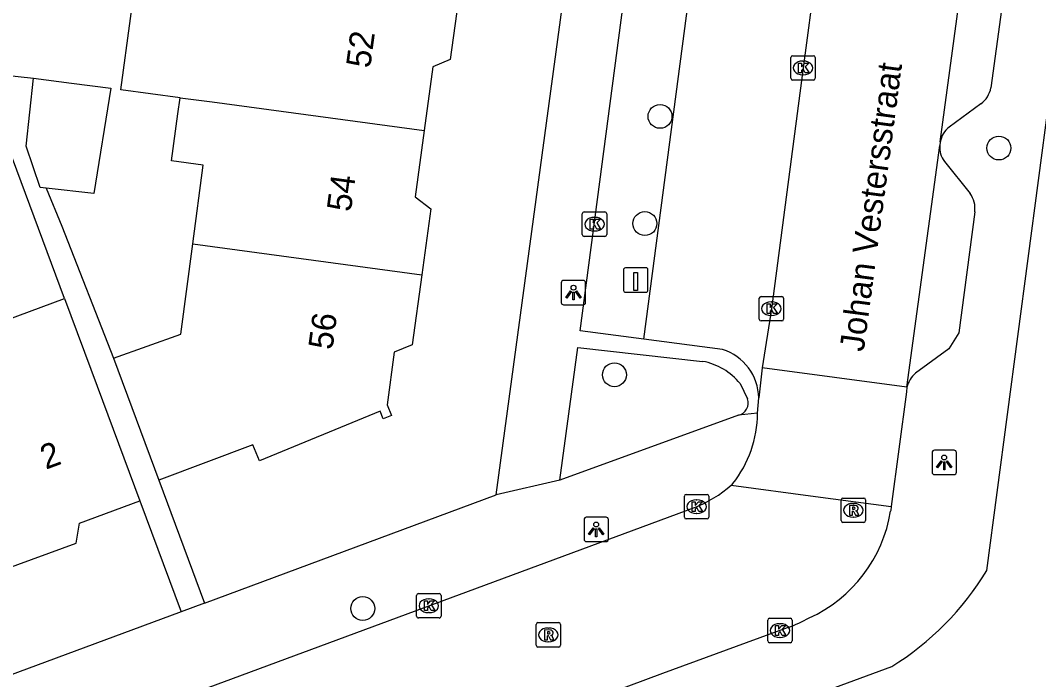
# Model space of a CAD drawing. Extents: x 161258 to 161838, y 380836 to 381727.
# Drawn here: x 161697.93 to 161739.61, y 381501.61 to 381528.61 of the extents above; entities that cross this region are included whole.
import ezdxf

# ---------------------------------------------------------------- set-up
doc = ezdxf.new("R2010")
doc.units = 0
for name, color, linetype in [('IMGEO_Boom', 7, 'Continuous'), ('IMGEO_Kolk', 7, 'Continuous'), ('IMGEO_Laadpaal', 7, 'Continuous'), ('IMGEO_Lichtpunt', 7, 'Continuous'), ('IMGEO_Openbare_ruimte_label', 7, 'Continuous'), ('IMGEO_Pand', 7, 'Continuous'), ('IMGEO_Pand_nummerreeks', 7, 'Continuous'), ('IMGEO_Rijbaan_lokaal_open', 7, 'Continuous'), ('IMGEO_Rioolput', 7, 'Continuous'), ('IMGEO_Voetpad_open', 7, 'Continuous')]:
    doc.layers.add(name, color=color, linetype=linetype)

msp = doc.modelspace()

# ---------------------------------------------------------------- linework, layer by layer
at = {"layer": 'IMGEO_Boom'}
for centre in [(161724.112, 381524.675), (161737.98, 381523.378), (161723.492, 381520.285), (161722.245, 381514.094), (161711.945, 381504.521)]:
    msp.add_circle(centre, 0.489, dxfattribs=at)
at = {"layer": 'IMGEO_Kolk'}
for p, q in [((161729.464, 381526.234), (161729.464, 381527.086)), ((161729.539, 381527.16), (161730.391, 381527.16)), ((161729.952, 381526.94), (161729.977, 381526.94)), ((161730.465, 381527.086), (161730.465, 381526.234)), ((161730.391, 381526.16), (161729.539, 381526.16)), ((161729.975, 381526.38), (161729.95, 381526.38)), ((161720.931, 381519.835), (161720.931, 381520.687)), ((161721.006, 381520.761), (161721.858, 381520.761)), ((161721.932, 381520.687), (161721.932, 381519.835)), ((161721.419, 381520.541), (161721.444, 381520.541)), ((161721.442, 381519.981), (161721.417, 381519.981)), ((161721.858, 381519.761), (161721.006, 381519.761)), ((161728.17, 381516.373), (161728.17, 381517.225)), ((161728.245, 381517.299), (161729.097, 381517.299)), ((161728.658, 381517.079), (161728.683, 381517.079)), ((161729.171, 381517.225), (161729.171, 381516.373)), ((161728.681, 381516.519), (161728.656, 381516.519)), ((161729.097, 381516.299), (161728.245, 381516.299)), ((161725.109, 381508.266), (161725.109, 381509.118)), ((161725.184, 381509.192), (161726.036, 381509.192)), ((161726.11, 381509.118), (161726.11, 381508.266)), ((161725.597, 381508.972), (161725.622, 381508.972)), ((161726.036, 381508.192), (161725.184, 381508.192)), ((161725.62, 381508.412), (161725.595, 381508.412)), ((161714.149, 381504.207), (161714.149, 381505.059)), ((161714.224, 381505.133), (161715.076, 381505.133)), ((161714.637, 381504.913), (161714.662, 381504.913)), ((161715.15, 381505.059), (161715.15, 381504.207)), ((161715.076, 381504.133), (161714.224, 381504.133)), ((161714.66, 381504.353), (161714.635, 381504.353)), ((161728.518, 381503.194), (161728.518, 381504.046)), ((161728.593, 381504.12), (161729.445, 381504.12)), ((161729.519, 381504.046), (161729.519, 381503.194)), ((161729.006, 381503.9), (161729.031, 381503.9)), ((161729.029, 381503.34), (161729.004, 381503.34)), ((161729.445, 381503.12), (161728.593, 381503.12))]:
    msp.add_line(p, q, dxfattribs=at)
for points in [[(161729.464, 381526.234), (161729.464, 381527.086)], [(161729.539, 381527.16), (161730.391, 381527.16)], [(161730.465, 381527.086), (161730.465, 381526.234)], [(161729.785, 381526.86), (161729.908, 381526.86), (161729.908, 381526.709), (161730.038, 381526.86), (161730.202, 381526.86), (161730.056, 381526.709), (161730.209, 381526.46), (161730.057, 381526.46), (161729.972, 381526.624), (161729.908, 381526.557), (161729.908, 381526.46), (161729.785, 381526.46), (161729.785, 381526.86)], [(161730.391, 381526.16), (161729.539, 381526.16)], [(161720.931, 381519.835), (161720.931, 381520.687)], [(161721.006, 381520.761), (161721.858, 381520.761)], [(161721.932, 381520.687), (161721.932, 381519.835)], [(161721.252, 381520.461), (161721.375, 381520.461), (161721.375, 381520.31), (161721.505, 381520.461), (161721.669, 381520.461), (161721.523, 381520.31), (161721.676, 381520.061), (161721.524, 381520.061), (161721.439, 381520.225), (161721.375, 381520.158), (161721.375, 381520.061), (161721.252, 381520.061), (161721.252, 381520.461)], [(161721.858, 381519.761), (161721.006, 381519.761)], [(161728.17, 381516.373), (161728.17, 381517.225)], [(161728.245, 381517.299), (161729.097, 381517.299)], [(161728.491, 381516.999), (161728.614, 381516.999), (161728.614, 381516.848), (161728.744, 381516.999), (161728.908, 381516.999), (161728.762, 381516.848), (161728.915, 381516.599), (161728.763, 381516.599), (161728.678, 381516.763), (161728.614, 381516.696), (161728.614, 381516.599), (161728.491, 381516.599), (161728.491, 381516.999)], [(161729.171, 381517.225), (161729.171, 381516.373)], [(161729.097, 381516.299), (161728.245, 381516.299)], [(161725.109, 381508.266), (161725.109, 381509.118)], [(161725.184, 381509.192), (161726.036, 381509.192)], [(161726.11, 381509.118), (161726.11, 381508.266)], [(161725.43, 381508.892), (161725.553, 381508.892), (161725.553, 381508.741), (161725.683, 381508.892), (161725.847, 381508.892), (161725.701, 381508.741), (161725.854, 381508.492), (161725.702, 381508.492), (161725.617, 381508.656), (161725.553, 381508.589), (161725.553, 381508.492), (161725.43, 381508.492), (161725.43, 381508.892)], [(161726.036, 381508.192), (161725.184, 381508.192)], [(161714.149, 381504.207), (161714.149, 381505.059)], [(161714.224, 381505.133), (161715.076, 381505.133)], [(161714.47, 381504.833), (161714.593, 381504.833), (161714.593, 381504.682), (161714.723, 381504.833), (161714.887, 381504.833), (161714.741, 381504.682), (161714.894, 381504.433), (161714.742, 381504.433), (161714.657, 381504.597), (161714.593, 381504.53), (161714.593, 381504.433), (161714.47, 381504.433), (161714.47, 381504.833)], [(161715.15, 381505.059), (161715.15, 381504.207)], [(161715.076, 381504.133), (161714.224, 381504.133)], [(161728.518, 381503.194), (161728.518, 381504.046)], [(161728.593, 381504.12), (161729.445, 381504.12)], [(161729.519, 381504.046), (161729.519, 381503.194)], [(161728.839, 381503.82), (161728.962, 381503.82), (161728.962, 381503.669), (161729.092, 381503.82), (161729.256, 381503.82), (161729.11, 381503.669), (161729.263, 381503.42), (161729.111, 381503.42), (161729.026, 381503.584), (161728.962, 381503.517), (161728.962, 381503.42), (161728.839, 381503.42), (161728.839, 381503.82)], [(161729.445, 381503.12), (161728.593, 381503.12)]]:
    msp.add_lwpolyline(points, dxfattribs=at)
for centre, start, end in [((161729.541, 381527.084), 91.552, 178.448), ((161729.541, 381527.084), 91.552, 178.448), ((161730.389, 381527.084), 1.552, 88.448), ((161730.389, 381527.084), 1.552, 88.448), ((161729.541, 381526.236), 181.552, 268.448), ((161729.541, 381526.236), 181.552, 268.448), ((161730.389, 381526.236), 271.552, 358.448), ((161730.389, 381526.236), 271.552, 358.448), ((161721.008, 381520.685), 91.552, 178.448), ((161721.008, 381520.685), 91.552, 178.448), ((161721.856, 381520.685), 1.552, 88.448), ((161721.856, 381520.685), 1.552, 88.448), ((161721.008, 381519.837), 181.552, 268.448), ((161721.008, 381519.837), 181.552, 268.448), ((161721.856, 381519.837), 271.552, 358.448), ((161721.856, 381519.837), 271.552, 358.448), ((161728.247, 381517.223), 91.552, 178.448), ((161728.247, 381517.223), 91.552, 178.448), ((161729.095, 381517.223), 1.552, 88.448), ((161729.095, 381517.223), 1.552, 88.448), ((161728.247, 381516.375), 181.552, 268.448), ((161728.247, 381516.375), 181.552, 268.448), ((161729.095, 381516.375), 271.552, 358.448), ((161729.095, 381516.375), 271.552, 358.448), ((161725.186, 381509.116), 91.552, 178.448), ((161725.186, 381509.116), 91.552, 178.448), ((161726.034, 381509.116), 1.552, 88.448), ((161726.034, 381509.116), 1.552, 88.448), ((161725.186, 381508.268), 181.552, 268.448), ((161725.186, 381508.268), 181.552, 268.448), ((161726.034, 381508.268), 271.552, 358.448), ((161726.034, 381508.268), 271.552, 358.448), ((161714.226, 381505.057), 91.552, 178.448), ((161714.226, 381505.057), 91.552, 178.448), ((161715.074, 381505.057), 1.552, 88.448), ((161715.074, 381505.057), 1.552, 88.448), ((161714.226, 381504.209), 181.552, 268.448), ((161714.226, 381504.209), 181.552, 268.448), ((161715.074, 381504.209), 271.552, 358.448), ((161715.074, 381504.209), 271.552, 358.448), ((161728.595, 381504.044), 91.552, 178.448), ((161728.595, 381504.044), 91.552, 178.448), ((161729.443, 381504.044), 1.552, 88.448), ((161729.443, 381504.044), 1.552, 88.448), ((161728.595, 381503.196), 181.552, 268.448), ((161728.595, 381503.196), 181.552, 268.448), ((161729.443, 381503.196), 271.552, 358.448), ((161729.443, 381503.196), 271.552, 358.448)]:
    msp.add_arc(centre, 0.0765, start, end, dxfattribs=at)
for centre, major_axis, ratio, start_param, end_param in [((161729.951, 381526.66), (-0.387, 0.002), 0.722429, 4.712389, 7.853982), ((161729.976, 381526.66), (-0.39, 0.002), 0.717154, 1.570796, 4.712389), ((161721.418, 381520.261), (-0.387, 0.002), 0.722429, 4.712389, 7.853982), ((161721.443, 381520.261), (-0.39, 0.002), 0.717154, 1.570796, 4.712389), ((161728.657, 381516.799), (-0.387, 0.002), 0.722429, 4.712389, 7.853982), ((161728.682, 381516.799), (-0.39, 0.002), 0.717154, 1.570796, 4.712389), ((161725.596, 381508.692), (-0.387, 0.002), 0.722429, 4.712389, 7.853982), ((161725.621, 381508.692), (-0.39, 0.002), 0.717154, 1.570796, 4.712389), ((161714.636, 381504.633), (-0.387, 0.002), 0.722429, 4.712389, 7.853982), ((161714.661, 381504.633), (-0.39, 0.002), 0.717154, 1.570796, 4.712389), ((161729.005, 381503.62), (-0.387, 0.002), 0.722429, 4.712389, 7.853982), ((161729.03, 381503.62), (-0.39, 0.002), 0.717154, 1.570796, 4.712389)]:
    msp.add_ellipse(centre, major_axis=major_axis, ratio=ratio, start_param=start_param, end_param=end_param, dxfattribs=at)
at = {"layer": 'IMGEO_Laadpaal'}
for p, q in [((161722.619, 381518.387), (161722.619, 381517.546)), ((161722.619, 381518.387), (161722.619, 381517.546)), ((161723.535, 381518.471), (161722.694, 381518.471)), ((161723.535, 381518.471), (161722.694, 381518.471)), ((161723.619, 381517.555), (161723.619, 381518.396)), ((161723.619, 381517.555), (161723.619, 381518.396)), ((161722.703, 381517.471), (161723.544, 381517.471)), ((161722.703, 381517.471), (161723.544, 381517.471))]:
    msp.add_line(p, q, dxfattribs=at)
msp.add_lwpolyline([(161723.034, 381518.284), (161723.194, 381518.284), (161723.194, 381517.551), (161723.034, 381517.551), (161723.034, 381518.284)], dxfattribs=at)
for centre, start, end in [((161722.697, 381518.393), 92.4484, 184.2845), ((161722.697, 381518.393), 92.4484, 184.2845), ((161723.541, 381518.393), 2.4484, 94.2845), ((161723.541, 381518.393), 2.4484, 94.2845), ((161722.697, 381517.549), 182.4484, 274.2845), ((161722.697, 381517.549), 182.4484, 274.2845), ((161723.541, 381517.549), 272.4484, 4.2845), ((161723.541, 381517.549), 272.4484, 4.2845)]:
    msp.add_arc(centre, 0.0779, start, end, dxfattribs=at)
at = {"layer": 'IMGEO_Lichtpunt'}
for p, q in [((161720.071, 381517.862), (161720.071, 381517.055)), ((161720.071, 381517.862), (161720.071, 381517.055)), ((161720.973, 381517.957), (161720.165, 381517.957)), ((161720.973, 381517.957), (161720.165, 381517.957)), ((161721.067, 381517.055), (161721.067, 381517.862)), ((161721.067, 381517.055), (161721.067, 381517.862)), ((161720.165, 381516.961), (161720.973, 381516.961)), ((161720.165, 381516.961), (161720.973, 381516.961)), ((161735.244, 381510.907), (161735.244, 381510.1)), ((161735.244, 381510.907), (161735.244, 381510.1)), ((161736.146, 381511.002), (161735.338, 381511.002)), ((161736.146, 381511.002), (161735.338, 381511.002)), ((161736.24, 381510.1), (161736.24, 381510.907)), ((161736.24, 381510.1), (161736.24, 381510.907)), ((161735.338, 381510.006), (161736.146, 381510.006)), ((161735.338, 381510.006), (161736.146, 381510.006)), ((161721.001, 381508.162), (161721.001, 381507.355)), ((161721.001, 381508.162), (161721.001, 381507.355)), ((161721.903, 381508.257), (161721.095, 381508.257)), ((161721.903, 381508.257), (161721.095, 381508.257)), ((161721.997, 381507.355), (161721.997, 381508.162)), ((161721.997, 381507.355), (161721.997, 381508.162)), ((161721.095, 381507.261), (161721.903, 381507.261)), ((161721.095, 381507.261), (161721.903, 381507.261))]:
    msp.add_line(p, q, dxfattribs=at)
for points in [[(161720.445, 381517.526), (161720.484, 381517.498), (161720.296, 381517.236), (161720.258, 381517.263), (161720.445, 381517.526)], [(161720.547, 381517.478), (161720.594, 381517.478), (161720.594, 381517.156), (161720.547, 381517.156), (161720.547, 381517.478)], [(161720.657, 381517.498), (161720.695, 381517.525), (161720.882, 381517.263), (161720.843, 381517.235), (161720.657, 381517.498)], [(161735.618, 381510.571), (161735.657, 381510.543), (161735.469, 381510.281), (161735.431, 381510.308), (161735.618, 381510.571)], [(161735.72, 381510.523), (161735.767, 381510.523), (161735.767, 381510.201), (161735.72, 381510.201), (161735.72, 381510.523)], [(161735.83, 381510.543), (161735.868, 381510.57), (161736.055, 381510.308), (161736.016, 381510.28), (161735.83, 381510.543)], [(161721.375, 381507.826), (161721.414, 381507.798), (161721.226, 381507.536), (161721.188, 381507.563), (161721.375, 381507.826)], [(161721.477, 381507.778), (161721.524, 381507.778), (161721.524, 381507.456), (161721.477, 381507.456), (161721.477, 381507.778)], [(161721.587, 381507.798), (161721.625, 381507.825), (161721.812, 381507.563), (161721.773, 381507.535), (161721.587, 381507.798)]]:
    msp.add_lwpolyline(points, dxfattribs=at)
for centre in [(161720.57, 381517.66), (161735.743, 381510.705), (161721.5, 381507.96)]:
    msp.add_circle(centre, 0.0994, dxfattribs=at)
for centre, start, end in [((161720.165, 381517.862), 90, 180), ((161720.165, 381517.862), 90, 180), ((161720.973, 381517.862), 0, 90), ((161720.973, 381517.862), 0, 90), ((161720.165, 381517.055), 180, 270), ((161720.165, 381517.055), 180, 270), ((161720.973, 381517.055), 270, 0), ((161720.973, 381517.055), 270, 360), ((161735.338, 381510.907), 90, 180), ((161735.338, 381510.907), 90, 180), ((161736.146, 381510.907), 0, 90), ((161736.146, 381510.907), 0, 90), ((161735.338, 381510.1), 180, 270), ((161735.338, 381510.1), 180, 270), ((161736.146, 381510.1), 270, 0), ((161736.146, 381510.1), 270, 360), ((161721.095, 381508.162), 90, 180), ((161721.095, 381508.162), 90, 180), ((161721.903, 381508.162), 0, 90), ((161721.903, 381508.162), 0, 90), ((161721.095, 381507.355), 180, 270), ((161721.095, 381507.355), 180, 270), ((161721.903, 381507.355), 270, 0), ((161721.903, 381507.355), 270, 360)]:
    msp.add_arc(centre, 0.0946, start, end, dxfattribs=at)
at = {"layer": 'IMGEO_Pand'}
for points in [[(161704.472, 381525.437), (161702.05, 381525.76), (161702.843, 381531.624)], [(161715.917, 381529.873), (161715.529, 381527.004), (161714.809, 381526.709), (161714.457, 381524.101)], [(161698.995, 381521.736), (161698.746, 381521.764), (161698.171, 381523.462), (161698.47, 381526.241)], [(161698.47, 381526.241), (161700.032, 381526.034), (161701.633, 381525.825), (161700.936, 381521.518), (161698.995, 381521.736)], [(161704.991, 381519.451), (161705.417, 381522.678), (161704.123, 381522.851), (161704.383, 381524.779), (161704.472, 381525.437)], [(161704.472, 381525.437), (161704.688, 381525.409), (161705.777, 381525.264), (161714.457, 381524.101)], [(161714.457, 381524.101), (161714.089, 381521.377), (161714.726, 381520.885), (161714.361, 381518.184)], [(161701.746, 381514.78), (161704.502, 381515.75), (161704.991, 381519.451)], [(161704.991, 381519.451), (161714.361, 381518.184)], [(161714.361, 381518.184), (161713.974, 381515.323), (161713.236, 381515.021), (161712.944, 381512.86), (161713.12, 381512.431), (161712.787, 381512.295), (161712.661, 381512.601), (161707.719, 381510.574), (161707.453, 381511.222), (161703.602, 381509.777)], [(161693.998, 381515.089), (161699.745, 381517.223)], [(161699.745, 381517.223), (161701.082, 381513.623), (161702.823, 381508.935)], [(161701.746, 381514.78), (161703.602, 381509.777)], [(161697.277, 381506.112), (161700.213, 381507.202), (161700.352, 381508.018), (161702.823, 381508.935)]]:
    msp.add_lwpolyline(points, dxfattribs=at)
at = {"layer": 'IMGEO_Rijbaan_lokaal_open'}
for points in [[(161735.58, 381523.626), (161737.448, 381537.445)], [(161730.473, 381530.472), (161729.966, 381526.66), (161728.672, 381516.798), (161728.292, 381514.383)], [(161735.58, 381523.626), (161735.56, 381523.476)], [(161734.218, 381513.579), (161735.56, 381523.476)], [(161728.292, 381514.383), (161728.151, 381513.143)], [(161734.218, 381513.579), (161728.292, 381514.383)], [(161734.218, 381513.579), (161734.197, 381513.389), (161733.573, 381508.694)], [(161728.107, 381512.517), (161728.151, 381513.143)], [(161727.024, 381509.572), (161727.058, 381509.605), (161727.093, 381509.638)], [(161727.024, 381509.572), (161730.479, 381509.109), (161733.573, 381508.694)], [(161658.225, 381483.74), (161671.265, 381488.572), (161693.452, 381496.782), (161725.523, 381508.66)], [(161733.573, 381508.694), (161733.551, 381508.53), (161733.548, 381508.51)], [(161729.353, 381503.742), (161729.019, 381503.62), (161724.209, 381501.861), (161701.588, 381493.419)]]:
    msp.add_lwpolyline(points, dxfattribs=at)
for centre, radius, start, end in [((161723.335, 381512.58), 4.773, 321.9479, 359.247), ((161723.726, 381513.308), 4.983, 291.1326, 311.4327), ((161727.791, 381509.437), 5.831, 294.5758, 350.8511), ((161726.46, 381511.258), 8.053, 291.0552, 297.8027)]:
    msp.add_arc(centre, radius, start, end, dxfattribs=at)
at = {"layer": 'IMGEO_Rioolput'}
for p, q in [((161731.599, 381509.046), (161732.451, 381509.046)), ((161731.524, 381508.12), (161731.524, 381508.972)), ((161732.012, 381508.826), (161732.037, 381508.826)), ((161732.525, 381508.972), (161732.525, 381508.12)), ((161732.035, 381508.266), (161732.01, 381508.266)), ((161732.451, 381508.046), (161731.599, 381508.046)), ((161719.041, 381503.016), (161719.041, 381503.868)), ((161719.116, 381503.942), (161719.968, 381503.942)), ((161719.529, 381503.722), (161719.554, 381503.722)), ((161720.042, 381503.868), (161720.042, 381503.016)), ((161719.552, 381503.162), (161719.527, 381503.162)), ((161719.968, 381502.942), (161719.116, 381502.942))]:
    msp.add_line(p, q, dxfattribs=at)
for points in [[(161731.599, 381509.046), (161732.451, 381509.046)], [(161731.524, 381508.12), (161731.524, 381508.972)], [(161732.113, 381508.744), (161731.861, 381508.746), (161731.861, 381508.346)], [(161732.039, 381508.665), (161731.985, 381508.665), (161731.985, 381508.584)], [(161731.985, 381508.584), (161732.037, 381508.584)], [(161732.525, 381508.972), (161732.525, 381508.12)], [(161731.861, 381508.346), (161731.985, 381508.346), (161731.985, 381508.508), (161731.996, 381508.508)], [(161732.043, 381508.479), (161732.114, 381508.346), (161732.254, 381508.346), (161732.189, 381508.472)], [(161732.451, 381508.046), (161731.599, 381508.046)], [(161719.041, 381503.016), (161719.041, 381503.868)], [(161719.116, 381503.942), (161719.968, 381503.942)], [(161719.63, 381503.64), (161719.378, 381503.642), (161719.378, 381503.242)], [(161719.556, 381503.561), (161719.502, 381503.561), (161719.502, 381503.48)], [(161720.042, 381503.868), (161720.042, 381503.016)], [(161719.378, 381503.242), (161719.502, 381503.242), (161719.502, 381503.404), (161719.513, 381503.404)], [(161719.502, 381503.48), (161719.554, 381503.48)], [(161719.56, 381503.375), (161719.631, 381503.242), (161719.771, 381503.242), (161719.706, 381503.368)], [(161719.968, 381502.942), (161719.116, 381502.942)]]:
    msp.add_lwpolyline(points, dxfattribs=at)
for centre, radius, start, end in [((161731.601, 381508.97), 0.0765, 91.552, 178.448), ((161731.601, 381508.97), 0.0765, 91.552, 178.448), ((161732.449, 381508.97), 0.0765, 1.552, 88.448), ((161732.449, 381508.97), 0.0765, 1.552, 88.448), ((161732.021, 381508.773), 0.19, 274.7715, 282.9687), ((161732.045, 381508.569), 0.0964, 77.0061, 93.1865), ((161732.059, 381508.626), 0.0378, 276.6634, 79.6772), ((161732.112, 381508.634), 0.109, 350.3612, 89.416), ((161732.11, 381508.634), 0.112, 277.5842, 350.9817), ((161731.995, 381508.455), 0.0533, 26.0293, 88.6989), ((161732.094, 381508.419), 0.108, 29.5134, 73.7905), ((161731.601, 381508.122), 0.0765, 181.552, 268.448), ((161731.601, 381508.122), 0.0765, 181.552, 268.448), ((161732.449, 381508.122), 0.0765, 271.552, 358.448), ((161732.449, 381508.122), 0.0765, 271.552, 358.448), ((161719.118, 381503.866), 0.0765, 91.552, 178.448), ((161719.118, 381503.866), 0.0765, 91.552, 178.448), ((161719.562, 381503.465), 0.0964, 77.0061, 93.1865), ((161719.629, 381503.53), 0.109, 350.3612, 89.416), ((161719.966, 381503.866), 0.0765, 1.552, 88.448), ((161719.966, 381503.866), 0.0765, 1.552, 88.448), ((161719.512, 381503.351), 0.0533, 26.0293, 88.6989), ((161719.538, 381503.669), 0.19, 274.7715, 282.9687), ((161719.576, 381503.522), 0.0378, 276.6634, 79.6772), ((161719.627, 381503.53), 0.112, 277.5842, 350.9817), ((161719.611, 381503.315), 0.108, 29.5134, 73.7905), ((161719.118, 381503.018), 0.0765, 181.552, 268.448), ((161719.118, 381503.018), 0.0765, 181.552, 268.448), ((161719.966, 381503.018), 0.0765, 271.552, 358.448), ((161719.966, 381503.018), 0.0765, 271.552, 358.448)]:
    msp.add_arc(centre, radius, start, end, dxfattribs=at)
for centre, major_axis, ratio, start_param, end_param in [((161732.011, 381508.546), (-0.387, 0.002), 0.722429, 4.712389, 7.853982), ((161732.036, 381508.546), (-0.39, 0.002), 0.717154, 1.570796, 4.712389), ((161719.528, 381503.442), (-0.387, 0.002), 0.722429, 4.712389, 7.853982), ((161719.553, 381503.442), (-0.39, 0.002), 0.717154, 1.570796, 4.712389)]:
    msp.add_ellipse(centre, major_axis=major_axis, ratio=ratio, start_param=start_param, end_param=end_param, dxfattribs=at)
at = {"layer": 'IMGEO_Voetpad_open'}
for points in [[(161717.412, 381509.172), (161725.791, 381571.18)], [(161723.447, 381515.547), (161720.85, 381515.886), (161720.838, 381515.888), (161724.557, 381544.042), (161725.131, 381548.374), (161727.76, 381548.004)], [(161737.48, 381506.08), (161741.711, 381538.033)], [(161738.828, 381534.45), (161737.653, 381525.849)], [(161723.447, 381515.547), (161725.287, 381529.523)], [(161693.486, 381525.558), (161688.074, 381526.15), (161688.236, 381527.342), (161698.47, 381526.241)], [(161737.244, 381525.192), (161735.942, 381524.239)], [(161699.745, 381517.223), (161697.617, 381522.953)], [(161735.749, 381522.833), (161736.806, 381521.513)], [(161698.995, 381521.736), (161699.626, 381520.176), (161701.746, 381514.78)], [(161736.993, 381520.77), (161736.336, 381515.815), (161735.927, 381515.15), (161734.57, 381514.162)], [(161726.673, 381515.126), (161723.447, 381515.547)], [(161720.005, 381509.784), (161720.744, 381515.207), (161725.856, 381514.642)], [(161727.388, 381513.732), (161727.694, 381513.11)], [(161727.319, 381512.433), (161720.005, 381509.784)], [(161728.107, 381512.517), (161727.319, 381512.433)], [(161703.602, 381509.777), (161705.469, 381504.742)], [(161720.005, 381509.784), (161717.412, 381509.172)], [(161705.469, 381504.742), (161717.412, 381509.172)], [(161702.823, 381508.935), (161704.512, 381504.387)], [(161705.469, 381504.742), (161704.512, 381504.387)], [(161704.512, 381504.387), (161692.684, 381500), (161641.589, 381481.048)], [(161703.642, 381491.064), (161721.654, 381497.729), (161727.792, 381500), (161733.594, 381502.147)]]:
    msp.add_lwpolyline(points, dxfattribs=at)
for centre, radius, start, end in [((161736.614, 381526.04), 1.057, 306.6137, 349.5796), ((161736.576, 381523.451), 1.011, 128.8184, 170.0546), ((161736.507, 381523.405), 0.95, 175.726, 217.0337), ((161735.955, 381520.904), 1.046, 352.6535, 35.6004), ((161726.036, 381513.109), 2.115, 0.9246, 72.4724), ((161725.389, 381512.111), 2.573, 39.0335, 79.5463), ((161735.313, 381513.316), 1.126, 131.27, 166.485), ((161727.198, 381512.943), 0.524, 283.3968, 18.6378), ((161727.45, 381512.104), 11.7, 301.6772, 329.0116)]:
    msp.add_arc(centre, radius, start, end, dxfattribs=at)

# ---------------------------------------------------------------- texts
at = {"layer": 'IMGEO_Openbare_ruimte_label'}
msp.add_text('Johan Vestersstraat', height=1, rotation=82.4129, dxfattribs=at).set_placement((161732.446, 381515.01))
at = {"layer": 'IMGEO_Pand_nummerreeks'}
for s, rotation, p in [('52', 82.3627, (161712.248, 381526.621)), ('54', 82.3627, (161711.458, 381520.737)), ('56', 82.3054, (161710.702, 381515.087)), ('2', 20.2099, (161698.973, 381510.202))]:
    msp.add_text(s, height=1, rotation=rotation, dxfattribs=at).set_placement(p)

doc.saveas('drawing.dxf')
